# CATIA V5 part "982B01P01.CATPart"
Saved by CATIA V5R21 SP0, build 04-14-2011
Part number: 982B01P01
Bounding box of the stored display mesh (mm): x -33.4 to 33.4, y -100 to 100, z -8 to 9.3
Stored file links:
  C:\Users\ALI OZGUN\Desktop\alhan\982B01P01.CATPart
  C:\Users\ALI OZGUN\Desktop\alhan\943B01P01.CATPart
  C:\Users\ALI OZGUN\Desktop\alhan\950B01P01.CATPart
  C:\Users\ALI OZGUN\Desktop\alhan\Product1.CATProduct
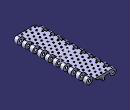
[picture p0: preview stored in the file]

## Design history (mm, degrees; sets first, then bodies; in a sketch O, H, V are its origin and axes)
Body1 (main body)
Body2
  Sketch1 on zx-plane, origin (0, 0, 0), H (-1, 0, 0), V (0, 0, 1)
    construction line L1 (25.4, 8) -> (25.4, -8)
    line L2 (25.4, -8) -> (-25.4, -8)
    construction line L3 (-25.4, -8) -> (-25.4, 8)
    line L4 (-25.4, 8) -> (25.4, 8)
    point P3 (-25.4, -8)
    arc A1 centre (25.4, 0) radius 8 from (25.4, 8) to (25.4, -8) cw
    arc A2 centre (-25.4, 0) radius 8 from (-25.4, 8) to (-25.4, -8) ccw
    point P7 (-25.4, -8)
    length L4 = 50.8
    length L3 = 16
    vertical: L1 V, L3 V
    horizontal: L2 H, L4 H
    equidistance: L1 L3 O, L2 L4 O
    tangency: A1 L2, A2 L4, A2 L2, L4 A1
    coincidence: P7 L2, P3 P7
  Pad1: profile Sketch1, direction (0, 1, 0), length 100, mirrored extent
  Sketch2 on zx-plane, origin (0, 0, 0), H (-1, 0, 0), V (0, 0, 1)
    circle A1 centre (25.4, 0) radius 3.15
    circle A2 centre (-25.4, 0) radius 3.15
  Pocket1: profile Sketch2, direction (0, -1, 0), length 204, mirrored extent
  Body3 "aramesefa"
    Sketch3 on face of Pad1 from Sketch1.L4, origin (0, 0, 8), H (1, 0, 0), V (0, 1, 0)
      line L1 (21.5, -80) -> (55.8232, -80)
      line L2 (55.8232, -80) -> (55.8232, -90.5)
      line L3 (55.8232, -90.5) -> (21.5, -90.5)
      line L4 (21.5, -90.5) -> (21.5, -80)
      reference projected line E1 (-25.4, -100) -> (25.4, -100) from edge [start face of Pad1 | face of Pad1 from Sketch1.L4]
      line L5 (-54.1233, -90) -> (-21.5, -90)
      line L6 (-21.5, -90) -> (-21.5, -100.5)
      line L7 (-21.5, -100.5) -> (-54.1233, -100.5)
      line L8 (-54.1233, -100.5) -> (-54.1233, -90)
      reference projected line E2 (-25.4, -100) -> (25.4, -100) from edge [start face of Pad1 | face of Pad1 from Sketch1.L4]
      distance L1 L3 = 10.5
      distance L3 E1 = 9.5
      distance L4 V = 21.5
      distance L5 L3 = 0.5
      distance L7 E2 = 0.5
      distance L6 L4 = 43
      horizontal: L1 H, L3 H, L5 H, L7 H
      vertical: L2 V, L4 V, L6 V, L8 V
    Pad2: profile Sketch3, direction (0, 0, 1), length 20, mirrored extent
    RectPattern1: of the body so far, direction 1 instances 10, spacing 20, along yz-plane
  Remove1: tool Body3
  Body4 "ALTBOSLUK"
    Sketch4 on zx-plane, origin (0, 0, 0), H (-1, 0, 0), V (0, 0, 1)
      line L1 (48.9583, 0) -> (33.4, 0)
      arc A1 centre (25.4, 0) radius 8 from (17.4, 0) to (33.4, 0) ccw
      line L2 (17.4, 0) -> (17.4, 0.2)
      arc A2 centre (15.4, 0.2) radius 2 from (17.4, 0.2) to (15.4, 2.2) ccw
      line L3 (15.4, 2.2) -> (5.5215, 2.2)
      arc A3 centre (5.5215, 0.2) radius 2 from (5.5215, 2.2) to (3.5325, 0.4091) ccw
      line L4 (3.5325, 0.4091) -> (2.9836, -4.8136)
      arc A4 centre (0, -4.4996) radius 3 from (-2.9836, -4.8136) to (2.9836, -4.8136) ccw
      line L5 (-2.9836, -4.8136) -> (-3.5325, 0.4091)
      arc A5 centre (-5.5215, 0.2) radius 2 from (-3.5325, 0.4091) to (-5.5215, 2.2) ccw
      line L6 (-5.5215, 2.2) -> (-15.4, 2.2)
      arc A6 centre (-15.4, 0.2) radius 2 from (-15.4, 2.2) to (-17.4, 0.2) ccw
      line L7 (-17.4, 0.2) -> (-17.4, 0)
      arc A7 centre (-25.4, 0) radius 8 from (-33.4, 0) to (-17.4, 0) ccw
      line L8 (-33.4, 0) -> (-46.3888, 0)
      line L9 (-46.3888, 0) -> (-46.3888, -17.807)
      line L10 (-46.3888, -17.807) -> (48.9583, -17.807)
      line L11 (48.9583, -17.807) -> (48.9583, 0)
      vertical: L9 V, L11 V
      horizontal: L10 H
    Pad3: profile Sketch4, direction (0, 1, 0), length 215, mirrored extent
  Remove2: tool Body4
  Body5 "KALANTIBOSALTMA"
    Sketch5 on face of Pad1 from Sketch1.L4, origin (0, 0, 8), H (1, 0, 0), V (0, 1, 0)
      line L1 (10, -80) -> (55.8232, -80)
      line L2 (55.8232, -80) -> (55.8232, -90.5)
      line L3 (55.8232, -90.5) -> (10, -90.5)
      line L4 (10, -90.5) -> (10, -80)
      reference projected line E1 (-25.4, -100) -> (25.4, -100) from edge [start face of Pad1 | face of Pad1 from Sketch1.L4]
      line L5 (-54.1233, -90) -> (-10, -90)
      line L6 (-10, -90) -> (-10, -100.5)
      line L7 (-10, -100.5) -> (-54.1233, -100.5)
      line L8 (-54.1233, -100.5) -> (-54.1233, -90)
      reference projected line E2 (-25.4, -100) -> (25.4, -100) from edge [start face of Pad1 | face of Pad1 from Sketch1.L4]
      distance L1 L3 = 10.5
      distance L3 E1 = 9.5
      distance L4 V = 10
      distance L5 L3 = 0.5
      distance L7 E2 = 0.5
      distance L6 L4 = 20
      horizontal: L1 H, L3 H, L5 H, L7 H
      vertical: L2 V, L4 V, L6 V, L8 V
    Pad4: profile Sketch5, direction (0, 0, 1), length 20, mirrored extent
    RectPattern2: of the body so far, direction 1 instances 10, spacing 20, along yz-plane
    Sketch6 on zx-plane, origin (0, 0, 0), H (-1, 0, 0), V (0, 0, 1)
      line L1 (108.0577, 2.2) -> (-84.5523, 2.2)
      fix: L1
    Pocket2: profile Sketch6, direction (0, -1, 0), length 215, mirrored extent
  Remove3: tool Body5
  Body6 "aramesefa ACILARI"
    Sketch7 on face of Pad1 from Sketch1.L4, origin (0, 0, 8), H (1, 0, 0), V (0, 1, 0)
      line L1 (21.5, -80) -> (55.8232, -80)
      line L2 (55.8232, -80) -> (55.8232, -90.5)
      line L3 (55.8232, -90.5) -> (21.5, -90.5)
      line L4 (21.5, -90.5) -> (21.5, -80)
      reference projected line E1 (-25.4, -100) -> (25.4, -100) from edge [start face of Pad1 | face of Pad1 from Sketch1.L4]
      line L5 (-54.1233, -90) -> (-21.5, -90)
      line L6 (-21.5, -90) -> (-21.5, -100.5)
      line L7 (-21.5, -100.5) -> (-54.1233, -100.5)
      line L8 (-54.1233, -100.5) -> (-54.1233, -90)
      reference projected line E2 (-25.4, -100) -> (25.4, -100) from edge [start face of Pad1 | face of Pad1 from Sketch1.L4]
      distance L1 L3 = 10.5
      distance L3 E1 = 9.5
      distance L4 V = 21.5
      distance L5 L3 = 0.5
      distance L7 E2 = 0.5
      distance L6 L4 = 43
      horizontal: L1 H, L3 H, L5 H, L7 H
      vertical: L2 V, L4 V, L6 V, L8 V
    Pad5: profile Sketch7, direction (0, 0, 1), length 20, mirrored extent
    Sketch8 on zx-plane, origin (0, 0, 0), H (-1, 0, 0), V (0, 0, 1)
      line L1 (67.6223, 8) -> (-70.015, 8)
      fix: L1
    Pocket3: profile Sketch8, direction (0, -1, 0), length 215, mirrored extent
    Draft1: Angle 45, Neutral face of Pocket3 from Sketch8.L1, PullDir face of Pocket3 from Sketch8.L1, SupportToDraft face of Pad5 from Sketch7.L6
    Draft2: Angle 45, Neutral face of Pocket3 from Sketch8.L1, PullDir face of Pocket3 from Sketch8.L1, SupportToDraft face of Pad5 from Sketch7.L4
    RectPattern3: of the body so far, direction 1 instances 10, spacing 20, along yz-plane
  Remove4: tool Body6
  Body7
    Sketch9 on face of Pad1 from Sketch1.L4, origin (0, 0, 8), H (1, 0, 0), V (0, 1, 0)
      construction line L1 (-40.1563, -95.25) -> (51.5563, -95.25)
      axis line L2 (-37.0014, -85.25) -> (45.0253, -85.25)
      reference projected line E1 (21.5, -80) -> (33.4, -80) from edge [face of Pad1 | face of Pad5]
      reference projected line E2 (-33.4, -90) -> (-21.5, -90) from edge [face of Pad1 | face of Pad5]
      circle A1 centre (17.1, -95.25) radius 2.1
      point P5 (17.1, -95.25)
      circle A2 centre (5.7, -95.25) radius 2.1
      point P6 (5.7, -95.25)
      circle A3 centre (-5.7, -95.25) radius 2.1
      point P7 (-5.7, -95.25)
      circle A4 centre (-17.1, -95.25) radius 2.1
      point P8 (-17.1, -95.25)
      circle A5 centre (0, -85.25) radius 2.1
      point P9 (0, -85.25)
      circle A6 centre (11.4, -85.25) radius 2.1
      point P10 (11.4, -85.25)
      circle A7 centre (-11.4, -85.25) radius 2.1
      point P11 (-11.4, -85.25)
      distance L2 E1 = 5.25
      distance L1 E2 = 5.25
      radius A1 = 2.1
      radius A2 = 2.1
      radius A3 = 2.1
      radius A4 = 2.1
      radius A7 = 2.1
      radius A5 = 2.1
      radius A6 = 2.1
      distance A6 A5 = 15.6
      distance A5 A7 = 15.6
      distance A1 A2 = 15.6
      distance A2 A3 = 15.6
      distance A3 A4 = 15.6
      distance P7 V = 5.7
      horizontal: L1 H, L2 H
      coincidence: P5 L1, P7 L1, P8 L1, P9 V, P9 L2, P10 L2, P11 L2
      midpoint: P6 L1
    Pad6: profile Sketch9, direction (0, 0, 1), length 1.3
    Chamfer1: length 1.3, angle 45, on edge [face of Pad6 from Sketch9.A6 | end face of Pad6]; end face of Pad6; edge [face of Pad6 from Sketch9.A7 | end face of Pad6]; edge [face of Pad6 from Sketch9.A4 | end face of Pad6]; edge [face of Pad6 from Sketch9.A3 | end face of Pad6]; edge [face of Pad6 from Sketch9.A2 | end face of Pad6]; edge [face of Pad6 from Sketch9.A1 | end face of Pad6]
    Fillet1: radius 1.3, on end face of Pad6 (x6); edge [face of Chamfer1 | end face of Pad6]
    RectPattern4: of the body so far, direction 1 instances 10, spacing 20, along yz-plane
  Add1: tool Body7
  Sketch10 on zx-plane, origin (0, 0, 0), H (-1, 0, 0), V (0, 0, 1)
    line L1 (0, 72) -> (0, 6.9718)
    point P1 (0, 72)
    reference projected line E1 (-25.4, -8) -> (25.4, -8) from edge [face of Pad1 from Sketch1.L2 | end face of Pad1]
    distance P1 E1 = 80
    coincidence: P1 V
    vertical: L1 V
Body8
  Solid1: linked copy from another document
  Translate1: Direction yz-plane, Length 50.8, ToTransfor Solid1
